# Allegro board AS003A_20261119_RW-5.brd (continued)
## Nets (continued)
DGND: BD1.1 BD2.1 BD3.1 BD4.1 BD5.1 BD6.1 BD7.1 BD8.1 BD9.1 BD10.1 BD11.1 BD12.1 C1.2 C2.2 C3.2 C4.2 C5.2 C6.2 C7.2 C8.2 C9.2 C10.2 C11.2 C12.2 C13.2 C14.2 C15.2 C16.2 C17.2 C18.2 C19.2 C20.2 C21.2 C22.2 C23.2 C24.2 C25.2 C26.2 C27.2 C28.2 C29.2 C30.2 C31.2 C32.2 C33.2 C34.2 C35.2 C36.2 C37.2 C38.2 C39.2 C40.2 C41.2 C42.2 C43.2 C44.2 C45.2 C46.2 C47.2 C48.2 C49.2 C50.2 C51.2 C52.2 C53.2 C54.2 C55.2 C56.2 C57.2 C58.2 C59.2 C60.2 C61.2 C62.2 C63.2 C64.2 C65.2 C66.2 C67.2 C68.2 C69.2 C70.2 C71.2 C72.2 C73.2 C74.2 C75.2 C76.2 C77.2 C78.2 C79.2 C80.2 C81.2 C82.2 C83.2 C84.2 C85.2 C86.2 C87.2 C88.2 C89.2 C90.2 C91.2 C92.2 C93.2 C94.2 C95.2 C96.2 C97.2 C98.2 C99.2 C100.2 C101.2 C102.2 C103.2 C104.2 C105.2 C106.2 C107.2 C108.2 C109.2 C110.2 C111.2 C112.2 C113.2 C114.2 C115.2 C116.2 C117.2 C118.2 C119.2 C120.2 C121.2 C122.2 C123.2 C124.2 C125.2 C126.2 C127.2 C128.2 C129.2 C130.2 C131.2 C132.2 C133.2 C134.2 C135.2 C136.2 C137.2 C138.2 C139.2 C140.2 C141.2 C142.2 C143.2 C144.2 C145.2 C146.2 C147.2 C148.2 C149.2 C150.2 C151.2 C152.2 C153.2 C154.2 C155.2 C156.2 C157.2 C158.2 C159.2 C160.2 C161.2 C162.2 C163.2 C164.2 C165.2 C166.2 C167.2 C168.2 C169.2 C170.2 C171.2 C172.2 C173.2 C174.2 C175.2 C176.2 C177.2 C178.2 C179.2 C180.2 C181.2 C182.2 C183.2 C184.2 C185.2 C186.2 C187.2 C188.2 C189.2 C190.2 C191.2 C192.2 C193.2 C194.2 C195.2 C196.2 C197.2 C198.2 C199.2 C200.2 C201.2 C202.2 C203.2 C204.2 C205.2 C206.2 C207.2 C208.2 C209.2 C210.2 C211.2 C212.2 C213.2 C214.2 C215.2 C216.2 C217.2 C218.2 C219.2 C220.2 C221.2 C222.2 C223.2 C224.2 C225.2 C226.2 C227.2 C228.2 C229.2 C230.2 C249.2 C250.2 C251.2 C285.2 C286.2 C287.2 C288.2 C289.2 C290.2 C291.2 C292.2 C293.2 C294.2 C295.2 C296.2 C297.2 C298.2 C299.2 C300.2 C332.2 C333.2 C334.2 C335.2 C336.2 C337.2 C338.2 C339.2 C340.2 C341.2 C342.2 C343.2 C344.2 C345.2 C346.2 C347.2 C348.2 C349.2 C350.2 C351.2 C352.2 C353.2 C354.2 C355.2 C356.2 C357.2 C358.2 C359.2 C360.2 C361.2 C362.2 C363.2 C364.2 C365.2 C366.2 C367.2 C368.2 C369.2 C370.2 C371.2 C372.2 C373.2 C374.2 C375.2 C376.2 C377.2 C378.2 C379.2 C380.2 C381.2 C382.2 C383.2 C384.2 C385.2 C386.2 C387.2 C388.2 C389.2 C390.2 C391.2 C392.2 C393.2 C394.2 C395.2 C396.2 C397.2 C398.2 C399.2 C400.2 C401.2 C402.2 C403.2 C404.2 C405.2 C406.2 C407.2 C408.2 C409.2 C410.2 C411.2 C412.2 C413.2 C414.2 C415.2 C416.2 C417.2 C418.2 C419.2 C420.2 C421.2 C422.2 C423.2 C424.2 C425.2 C426.2 C427.2 C428.2 C429.2 C430.2 C431.2 C432.2 C433.2 C434.2 C435.2 C436.2 C437.2 C438.2 C439.2 C440.2 C441.2 C442.2 C443.2 C444.2 C445.2 C446.2 C447.2 C448.2 C449.2 C450.2 C451.2 C452.2 C453.2 C454.2 C455.2 C456.2 C457.2 C458.2 C459.2 C460.2 C461.2 C462.2 C463.2 C464.2 C465.2 C466.2 C467.2 C468.2 C469.2 CSDPS225.B2 CSDPS225.B4 CSDPS225.B6 CSDPS225.B8 CSDPS225.B10 CSDPS225.B12 CSDPS225.B14 CSDPS225.B16 CSDPS225.C1 CSDPS225.C3 CSDPS225.C5 CSDPS225.C7 CSDPS225.C9 CSDPS225.C11 CSDPS225.C13 CSDPS225.C15 CSDPS226.B2 CSDPS226.B4 CSDPS226.B6 CSDPS226.B8 CSDPS226.B10 CSDPS226.B12 CSDPS226.B14 CSDPS226.B16 CSDPS226.C1 CSDPS226.C3 CSDPS226.C5 CSDPS226.C7 CSDPS226.C9 CSDPS226.C11 CSDPS226.C13 CSDPS226.C15 CSDPS229.B2 CSDPS229.B4 CSDPS229.B6 CSDPS229.B8 CSDPS229.B10 CSDPS229.B12 CSDPS229.B14 CSDPS229.B16 CSDPS229.C1 CSDPS229.C3 CSDPS229.C5 CSDPS229.C7 CSDPS229.C9 CSDPS229.C11 CSDPS229.C13 CSDPS229.C15 CSDPS425.B2 CSDPS425.B4 CSDPS425.B6 CSDPS425.B8 CSDPS425.B10 CSDPS425.B12 CSDPS425.B14 CSDPS425.B16 CSDPS425.C1 CSDPS425.C3 CSDPS425.C5 CSDPS425.C7 CSDPS425.C9 CSDPS425.C11 CSDPS425.C13 CSDPS425.C15 CSDPS426.B2 CSDPS426.B4 CSDPS426.B6 CSDPS426.B8 CSDPS426.B10 CSDPS426.B12 CSDPS426.B14 CSDPS426.B16 CSDPS426.C1 CSDPS426.C3 CSDPS426.C5 CSDPS426.C7 CSDPS426.C9 CSDPS426.C11 CSDPS426.C13 CSDPS426.C15 CSDPS429.B2 CSDPS429.B4 CSDPS429.B6 CSDPS429.B8 CSDPS429.B10 CSDPS429.B12 CSDPS429.B14 CSDPS429.B16 CSDPS429.C1 CSDPS429.C3 CSDPS429.C5 CSDPS429.C7 CSDPS429.C9 CSDPS429.C11 CSDPS429.C13 CSDPS429.C15 D101.A1 D101.A2 D101.A3 D101.A4 D101.A5 D101.A6 D101.A7 D101.A8 D101.A9 D101.A10 D101.A11 D101.A12 D101.A13 D101.A14 D101.A15 D101.A16 D101.B1 D101.B2 D101.B3 D101.B4 D101.B5 D101.B6 D101.B7 D101.B8 D101.B9 D101.B10 D101.B11 D101.B12 D101.B13 D101.B14 D101.B15 D101.B16 D102.A1 D102.A2 D102.A3 D102.A4 D102.A5 D102.A6 D102.A7 D102.A8 D102.A9 D102.A10 D102.A11 D102.A12 D102.A13 D102.A14 D102.A15 D102.A16 D102.B1 D102.B2 D102.B3 D102.B4 D102.B5 D102.B6 D102.B7 D102.B8 D102.B9 D102.B10 D102.B11 D102.B12 D102.B13 D102.B14 D102.B15 D102.B16 D103.A1 D103.A2 D103.A3 D103.A4 D103.A5 D103.A6 D103.A7 D103.A8 D103.A9 D103.A10 D103.A11 D103.A12 D103.A13 D103.A14 D103.A15 D103.A16 D103.B1 D103.B2 D103.B3 D103.B4 D103.B5 D103.B6 D103.B7 D103.B8 D103.B9 D103.B10 D103.B11 D103.B12 D103.B13 D103.B14 D103.B15 D103.B16 D104.A1 D104.A2 D104.A3 D104.A4 D104.A5 D104.A6 D104.A7 D104.A8 D104.A9 D104.A10 D104.A11 D104.A12 D104.A13 D104.A14 D104.A15 D104.A16 D104.B1 D104.B2 D104.B3 D104.B4 D104.B5 D104.B6 D104.B7 D104.B8 D104.B9 D104.B10 D104.B11 D104.B12 D104.B13 D104.B14 D104.B15 D104.B16 D105.A1 D105.A2 D105.A3 D105.A4 D105.A5 D105.A6 D105.A7 D105.A8 D105.A9 D105.A10 D105.A11 D105.A12 D105.A13 D105.A14 D105.A15 D105.A16 D105.B1 D105.B2 D105.B3 D105.B4 D105.B5 D105.B6 D105.B7 D105.B8 D105.B9 D105.B10 D105.B11 D105.B12 D105.B13 D105.B14 D105.B15 D105.B16 D106.A1 D106.A2 D106.A3 D106.A4 D106.A5 D106.A6 D106.A7 D106.A8 D106.A9 D106.A10 D106.A11 D106.A12 D106.A13 D106.A14 D106.A15 D106.A16 D106.B1 D106.B2 D106.B3 D106.B4 D106.B5 D106.B6 D106.B7 D106.B8 D106.B9 D106.B10 D106.B11 D106.B12 D106.B13 D106.B14 D106.B15 D106.B16 D107.A1 D107.A2 D107.A3 D107.A4 D107.A5 D107.A6 D107.A7 D107.A8 D107.A9 D107.A10 D107.A11 D107.A12 D107.A13 D107.A14 D107.A15 D107.A16 D107.B1 D107.B2 D107.B3 D107.B4 D107.B5 D107.B6 D107.B7 D107.B8 D107.B9 D107.B10 D107.B11 D107.B12 D107.B13 D107.B14 D107.B15 D107.B16 D108.A1 D108.A2 D108.A3 D108.A4 D108.A5 D108.A6 D108.A7 D108.A8 D108.A9 D108.A10 D108.A11 D108.A12 D108.A13 D108.A14 D108.A15 D108.A16 D108.B1 D108.B2 D108.B3 D108.B4 D108.B5 D108.B6 D108.B7 D108.B8 D108.B9 D108.B10 D108.B11 D108.B12 D108.B13 D108.B14 D108.B15 D108.B16 D109.A1 D109.A2 D109.A3 D109.A4 D109.A5 D109.A6 D109.A7 D109.A8 D109.A9 D109.A10 D109.A11 D109.A12 D109.A13 D109.A14 D109.A15 D109.A16 D109.B1 D109.B2 D109.B3 D109.B4 D109.B5 D109.B6 D109.B7 D109.B8 D109.B9 D109.B10 D109.B11 D109.B12 D109.B13 D109.B14 D109.B15 D109.B16 D110.A1 D110.A2 D110.A3 D110.A4 D110.A5 D110.A6 D110.A7 D110.A8 D110.A9 D110.A10 D110.A11 D110.A12 D110.A13 D110.A14 D110.A15 D110.A16 D110.B1 D110.B2 D110.B3 D110.B4 D110.B5 D110.B6 D110.B7 D110.B8 D110.B9 D110.B10 D110.B11 D110.B12 D110.B13 D110.B14 D110.B15 D110.B16 D111.A1 D111.A2 D111.A3 D111.A4 D111.A5 D111.A6 D111.A7 D111.A8 D111.A9 D111.A10 D111.A11 D111.A12 D111.A13 D111.A14 D111.A15 D111.A16 D111.B1 D111.B2 D111.B3 D111.B4 D111.B5 D111.B6 D111.B7 D111.B8 D111.B9 D111.B10 D111.B11 D111.B12 D111.B13 D111.B14 D111.B15 D111.B16 D112.A1 D112.A2 D112.A3 D112.A4 D112.A5 D112.A6 D112.A7 D112.A8 D112.A9 D112.A10 D112.A11 D112.A12 D112.A13 D112.A14 D112.A15 D112.A16 D112.B1 D112.B2 D112.B3 D112.B4 D112.B5 D112.B6 D112.B7 D112.B8 D112.B9 D112.B10 D112.B11 D112.B12 D112.B13 D112.B14 D112.B15 D112.B16 D113.A1 D113.A2 D113.A3 D113.A4 D113.A5 D113.A6 D113.A7 D113.A8 D113.A9 D113.A10 D113.A11 D113.A12 D113.A13 D113.A14 D113.A15 D113.A16 D113.B1 D113.B2 D113.B3 D113.B4 D113.B5 D113.B6 D113.B7 D113.B8 D113.B9 D113.B10 D113.B11 D113.B12 D113.B13 D113.B14 D113.B15 D113.B16 D114.A1 D114.A2 D114.A3 D114.A4 D114.A5 D114.A6 D114.A7 D114.A8 D114.A9 D114.A10 D114.A11 D114.A12 D114.A13 D114.A14 D114.A15 D114.A16 D114.B1 D114.B2 D114.B3 D114.B4 D114.B5 D114.B6 D114.B7 D114.B8 D114.B9 D114.B10 D114.B11 D114.B12 D114.B13 D114.B14 D114.B15 D114.B16 D115.A1 D115.A2 D115.A3 D115.A4 D115.A5 D115.A6 D115.A7 D115.A8 D115.A9 D115.A10 D115.A11 D115.A12 D115.A13 D115.A14 D115.A15 D115.A16 D115.B1 D115.B2 D115.B3 D115.B4 D115.B5 D115.B6 D115.B7 D115.B8 D115.B9 D115.B10 D115.B11 D115.B12 D115.B13 D115.B14 D115.B15 D115.B16 D116.A1 D116.A2 D116.A3 D116.A4 D116.A5 D116.A6 D116.A7 D116.A8 D116.A9 D116.A10 D116.A11 D116.A12 D116.A13 D116.A14 D116.A15 D116.A16 D116.B1 D116.B2 D116.B3 D116.B4 D116.B5 D116.B6 D116.B7 D116.B8 D116.B9 D116.B10 D116.B11 D116.B12 D116.B13 D116.B14 D116.B15 D116.B16 D117.A1 D117.A2 D117.A3 D117.A4 D117.A5 D117.A6 D117.A7 D117.A8 D117.A9 D117.A10 D117.A11 D117.A12 D117.A13 D117.A14 D117.A15 D117.A16 D117.B1 D117.B2 D117.B3 D117.B4 D117.B5 D117.B6 D117.B7 D117.B8 D117.B9 D117.B10 D117.B11 D117.B12 D117.B13 D117.B14 D117.B15 D117.B16 D118.A1 D118.A2 D118.A3 D118.A4 D118.A5 D118.A6 D118.A7 D118.A8 D118.A9 D118.A10 D118.A11 D118.A12 D118.A13 D118.A14 D118.A15 D118.A16 D118.B1 D118.B2 D118.B3 D118.B4 D118.B5 D118.B6 D118.B7 D118.B8 D118.B9 D118.B10 D118.B11 D118.B12 D118.B13 D118.B14 D118.B15 D118.B16 D119.A1 D119.A2 D119.A3 D119.A4 D119.A5 D119.A6 D119.A7 D119.A8 D119.A9 D119.A10 D119.A11 D119.A12 D119.A13 D119.A14 D119.A15 D119.A16 D119.B1 D119.B2 D119.B3 D119.B4 D119.B5 D119.B6 D119.B7 D119.B8 D119.B9 D119.B10 D119.B11 D119.B12 D119.B13 D119.B14 D119.B15 D119.B16 D120.A1 D120.A2 D120.A3 D120.A4 D120.A5 D120.A6 D120.A7 D120.A8 D120.A9 D120.A10 D120.A11 D120.A12 D120.A13 D120.A14 D120.A15 D120.A16 D120.B1 D120.B2 D120.B3 D120.B4 D120.B5 D120.B6 D120.B7 D120.B8 D120.B9 D120.B10 D120.B11 D120.B12 D120.B13 D120.B14 D120.B15 D120.B16 D121.A1 D121.A2 D121.A3 D121.A4 D121.A5 D121.A6 D121.A7 D121.A8 D121.A9 D121.A10 D121.A11 D121.A12 D121.A13 D121.A14 D121.A15 D121.A16 D121.B1 D121.B2 D121.B3 D121.B4 D121.B5 D121.B6 D121.B7 D121.B8 D121.B9 D121.B10 D121.B11 D121.B12 D121.B13 D121.B14 D121.B15 D121.B16 D122.A1 D122.A2 D122.A3 D122.A4 D122.A5 D122.A6 D122.A7 D122.A8 D122.A9 D122.A10 D122.A11 D122.A12 D122.A13 D122.A14 D122.A15 D122.A16 D122.B1 D122.B2 D122.B3 D122.B4 D122.B5 D122.B6 D122.B7 D122.B8 D122.B9 D122.B10 D122.B11 D122.B12 D122.B13 D122.B14 D122.B15 D122.B16 D123.A1 D123.A2 D123.A3 D123.A4 D123.A5 D123.A6 D123.A7 D123.A8 D123.A9 D123.A10 D123.A11 D123.A12 D123.A13 D123.A14 D123.A15 D123.A16 D123.B1 D123.B2 D123.B3 D123.B4 D123.B5 D123.B6 D123.B7 D123.B8 D123.B9 D123.B10 D123.B11 D123.B12 D123.B13 D123.B14 D123.B15 D123.B16 D124.A1 D124.A2 D124.A3 D124.A4 D124.A5 D124.A6 D124.A7 D124.A8 D124.A9 D124.A10 D124.A11 D124.A12 D124.A13 D124.A14 D124.A15 D124.A16 D124.B1 D124.B2 D124.B3 D124.B4 D124.B5 D124.B6 D124.B7 D124.B8 D124.B9 D124.B10 D124.B11 D124.B12 D124.B13 D124.B14 D124.B15 D124.B16 D125.A1 D125.A2 D125.A3 D125.A4 D125.A5 D125.A6 D125.A7 D125.A8 D125.A9 D125.A10 D125.A11 D125.A12 D125.A13 D125.A14 D125.A15 D125.A16 D125.B1 D125.B2 D125.B3 D125.B4 D125.B5 D125.B6 D125.B7 D125.B8 D125.B9 D125.B10 D125.B11 D125.B12 D125.B13 D125.B14 D125.B15 D125.B16 D126.A1 D126.A2 D126.A3 D126.A4 D126.A5 D126.A6 D126.A7 D126.A8 D126.A9 D126.A10 D126.A11 D126.A12 D126.A13 D126.A14 D126.A15 D126.A16 D126.B1 D126.B2 D126.B3 D126.B4 D126.B5 D126.B6 D126.B7 D126.B8 D126.B9 D126.B10 D126.B11 D126.B12 D126.B13 D126.B14 D126.B15 D126.B16 D127.A1 D127.A2 D127.A3 D127.A4 D127.A5 D127.A6 D127.A7 D127.A8 D127.A9 D127.A10 D127.A11 D127.A12 D127.A13 D127.A14 D127.A15 D127.A16 D127.B1 D127.B2 D127.B3 D127.B4 D127.B5 D127.B6 D127.B7 D127.B8 D127.B9 D127.B10 D127.B11 D127.B12 D127.B13 D127.B14 D127.B15 D127.B16 D128.A1 D128.A2 D128.A3 D128.A4 D128.A5 D128.A6 D128.A7 D128.A8 D128.A9 D128.A10 D128.A11 D128.A12 D128.A13 D128.A14 D128.A15 D128.A16 D128.B1 D128.B2 D128.B3 D128.B4 D128.B5 D128.B6 D128.B7 D128.B8 D128.B9 D128.B10 D128.B11 D128.B12 D128.B13 D128.B14 D128.B15 D128.B16 D129.A1 D129.A2 D129.A3 D129.A4 D129.A5 D129.A6 D129.A7 D129.A8 D129.A9 D129.A10 D129.A11 D129.A12 D129.A13 D129.A14 D129.A15 D129.A16 D129.B1 D129.B2 D129.B3 D129.B4 D129.B5 D129.B6 D129.B7 D129.B8 D129.B9 D129.B10 D129.B11 D129.B12 D129.B13 D129.B14 D129.B15 D129.B16 D130.A1 D130.A2 D130.A3 D130.A4 D130.A5 D130.A6 D130.A7 D130.A8 D130.A9 D130.A10 D130.A11 D130.A12 D130.A13 D130.A14 D130.A15 D130.A16 D130.B1 D130.B2 D130.B3 D130.B4 D130.B5 D130.B6 D130.B7 D130.B8 D130.B9 D130.B10 D130.B11 D130.B12 D130.B13 D130.B14 D130.B15 D130.B16 D131.A1 D131.A2 D131.A3 D131.A4 D131.A5 D131.A6 D131.A7 D131.A8 D131.A9 D131.A10 D131.A11 D131.A12 D131.A13 D131.A14 D131.A15 D131.A16 D131.B1 D131.B2 D131.B3 D131.B4 D131.B5 D131.B6 D131.B7 D131.B8 D131.B9 D131.B10 D131.B11 D131.B12 D131.B13 D131.B14 D131.B15 D131.B16 D132.A1 D132.A2 D132.A3 D132.A4 D132.A5 D132.A6 D132.A7 D132.A8 D132.A9 D132.A10 D132.A11 D132.A12 D132.A13 D132.A14 D132.A15 D132.A16 D132.B1 D132.B2 D132.B3 D132.B4 D132.B5 D132.B6 D132.B7 D132.B8 D132.B9 D132.B10 D132.B11 D132.B12 D132.B13 D132.B14 D132.B15 D132.B16 D217.A1 D217.A2 D217.A3 D217.A4 D217.A5 D217.A6 D217.A7 D217.A8 D217.A9 D217.A10 D217.A11 D217.A12 D217.A13 D217.A14 D217.A15 D217.A16 D217.B1 D217.B2 D217.B3 D217.B4 D217.B5 D217.B6 D217.B7 D217.B8 D217.B9 D217.B10 D217.B11 D217.B12 D217.B13 D217.B14 D217.B15 D217.B16 D218.A1 D218.A2 D218.A3 D218.A4 D218.A5 D218.A6 D218.A7 D218.A8 D218.A9 D218.A10 D218.A11 D218.A12 D218.A13 D218.A14 D218.A15 D218.A16 D218.B1 D218.B2 D218.B3 D218.B4 D218.B5 D218.B6 D218.B7 D218.B8 D218.B9 D218.B10 D218.B11 D218.B12 D218.B13 D218.B14 D218.B15 D218.B16 D219.A1 D219.A2 D219.A3 D219.A4 D219.A5 D219.A6 D219.A7 D219.A8 D219.A9 D219.A10 D219.A11 D219.A12 D219.A13 D219.A14 D219.A15 D219.A16 D219.B1 D219.B2 D219.B3 D219.B4 D219.B5 D219.B6 D219.B7 D219.B8 D219.B9 D219.B10 D219.B11 D219.B12 D219.B13 D219.B14 D219.B15 D219.B16 D220.A1 D220.A2 D220.A3 D220.A4 D220.A5 D220.A6 D220.A7 D220.A8 D220.A9 D220.A10 D220.A11 D220.A12 D220.A13 D220.A14 D220.A15 D220.A16 D220.B1 D220.B2 D220.B3 D220.B4 D220.B5 D220.B6 D220.B7 D220.B8 D220.B9 D220.B10 D220.B11 D220.B12 D220.B13 D220.B14 D220.B15 D220.B16 D221.A1 D221.A2 D221.A3 D221.A4 D221.A5 D221.A6 D221.A7 D221.A8 D221.A9 D221.A10 D221.A11 D221.A12 D221.A13 D221.A14 D221.A15 D221.A16 D221.B1 D221.B2 D221.B3 D221.B4 D221.B5 D221.B6 D221.B7 D221.B8 D221.B9 D221.B10 D221.B11 D221.B12 D221.B13 D221.B14 D221.B15 D221.B16 D222.A1 D222.A2 D222.A3 D222.A4 D222.A5 D222.A6 D222.A7 D222.A8 D222.A9 D222.A10 D222.A11 D222.A12 D222.A13 D222.A14 D222.A15 D222.A16 D222.B1 D222.B2 D222.B3 D222.B4 D222.B5 D222.B6 D222.B7 D222.B8 D222.B9 D222.B10 D222.B11 D222.B12 D222.B13 D222.B14 D222.B15 D222.B16 D223.A1 D223.A2 D223.A3 D223.A4 D223.A5 D223.A6 D223.A7 D223.A8 D223.A9 D223.A10 D223.A11 D223.A12 D223.A13 D223.A14 D223.A15 D223.A16 D223.B1 D223.B2 D223.B3 D223.B4 D223.B5 D223.B6 D223.B7 D223.B8 D223.B9 D223.B10 D223.B11 D223.B12 D223.B13 D223.B14 D223.B15 D223.B16 D224.A1 D224.A2 D224.A3 D224.A4 D224.A5 D224.A6 D224.A7 D224.A8 D224.A9 D224.A10 D224.A11 D224.A12 D224.A13 D224.A14 D224.A15 D224.A16 D224.B1 D224.B2 D224.B3 D224.B4 D224.B5 D224.B6 D224.B7 D224.B8 D224.B9 D224.B10 D224.B11 D224.B12 D224.B13 D224.B14 D224.B15 D224.B16 D227.A1 D227.A2 D227.A3 D227.A4 D227.A5 D227.A6 D227.A7 D227.A8 D227.A9 D227.A10 D227.A11 D227.A12 D227.A13 D227.A14 D227.A15 D227.A16 D227.A17 D227.B1 D227.B2 D227.B3 D227.B4 D227.B5 D227.B6 D227.B7 D227.B8 D227.B9 D227.B10 D227.B11 D227.B12 D227.B13 D227.B14 D227.B15 D227.B16 D227.B17 D228.A1 D228.A2 D228.A3 D228.A4 D228.A5 D228.A6 D228.A7 D228.A8 D228.A9 D228.A10 D228.A11 D228.A12 D228.A13 D228.A14 D228.A15 D228.A16 D228.A17 D228.B1 D228.B2 D228.B3 D228.B4 D228.B5 D228.B6 D228.B7 D228.B8 D228.B9 D228.B10 D228.B11 D228.B12 D228.B13 D228.B14 D228.B15 D228.B16 D228.B17 D231.A1 D231.A2 D231.A3 D231.A4 D231.A5 D231.A6 D231.A7 D231.A8 D231.A9 D231.A10 D231.A11 D231.A12 D231.A13 D231.A14 D231.A15 D231.A16 D231.A17 D231.B1 D231.B2 D231.B3 D231.B4 D231.B5 D231.B6 D231.B7 D231.B8 D231.B9 D231.B10 D231.B11 D231.B12 D231.B13 D231.B14 D231.B15 D231.B16 D231.B17 D232.A1 D232.A2 D232.A3 D232.A4 D232.A5 D232.A6 D232.A7 D232.A8 D232.A9 D232.A10 D232.A11 D232.A12 D232.A13 D232.A14 D232.A15 D232.A16 D232.A17 D232.B1 D232.B2 D232.B3 D232.B4 D232.B5 D232.B6 D232.B7 D232.B8 D232.B9 D232.B10 D232.B11 D232.B12 D232.B13 D232.B14 D232.B15 D232.B16 D232.B17 D301.A1 D301.A2 D301.A3 D301.A4 D301.A5 D301.A6 D301.A7 D301.A8 D301.A9 D301.A10 D301.A11 D301.A12 D301.A13 D301.A14 D301.A15 D301.A16 D301.B1 D301.B2 D301.B3 D301.B4 D301.B5 D301.B6 D301.B7 D301.B8 D301.B9 D301.B10 D301.B11 D301.B12 D301.B13 D301.B14 D301.B15 D301.B16 D302.A1 D302.A2 D302.A3 D302.A4 D302.A5 D302.A6 D302.A7 D302.A8 D302.A9 D302.A10 D302.A11 D302.A12 D302.A13 D302.A14 D302.A15 D302.A16 D302.B1 D302.B2 D302.B3 D302.B4 D302.B5 D302.B6 D302.B7 D302.B8 D302.B9 D302.B10 D302.B11 D302.B12 D302.B13 D302.B14 D302.B15 D302.B16 D303.A1 D303.A2 D303.A3 D303.A4 D303.A5 D303.A6 D303.A7 D303.A8 D303.A9 D303.A10 D303.A11 D303.A12 D303.A13 D303.A14 D303.A15 D303.A16 D303.B1 D303.B2 D303.B3 D303.B4 D303.B5 D303.B6 D303.B7 D303.B8 D303.B9 D303.B10 D303.B11 D303.B12 D303.B13 D303.B14 D303.B15 D303.B16 D304.A1 D304.A2 D304.A3 D304.A4 D304.A5 D304.A6 D304.A7 D304.A8 D304.A9 D304.A10 D304.A11 D304.A12 D304.A13 D304.A14 D304.A15 D304.A16 D304.B1 D304.B2 D304.B3 D304.B4 D304.B5 D304.B6 D304.B7 D304.B8 D304.B9 D304.B10 D304.B11 D304.B12 D304.B13 D304.B14 D304.B15 D304.B16 D305.A1 D305.A2 D305.A3 D305.A4 D305.A5 D305.A6 D305.A7 D305.A8 D305.A9 D305.A10 D305.A11 D305.A12 D305.A13 D305.A14 D305.A15 D305.A16 D305.B1 D305.B2 D305.B3 D305.B4 D305.B5 D305.B6 D305.B7 D305.B8 D305.B9 D305.B10 D305.B11 D305.B12 D305.B13 D305.B14 D305.B15 D305.B16 D306.A1 D306.A2 D306.A3 D306.A4 D306.A5 D306.A6 D306.A7 D306.A8 D306.A9 D306.A10 D306.A11 D306.A12 D306.A13 D306.A14 D306.A15 D306.A16 D306.B1 D306.B2 D306.B3 D306.B4 D306.B5 D306.B6 D306.B7 D306.B8 D306.B9 D306.B10 D306.B11 D306.B12 D306.B13 D306.B14 D306.B15 D306.B16 D307.A1 D307.A2 D307.A3 D307.A4 D307.A5 D307.A6 D307.A7 D307.A8 D307.A9 D307.A10 D307.A11 D307.A12 D307.A13 D307.A14 D307.A15 D307.A16 D307.B1 D307.B2 D307.B3 D307.B4 D307.B5 D307.B6 D307.B7 D307.B8 D307.B9 D307.B10 D307.B11 D307.B12 D307.B13 D307.B14 D307.B15 D307.B16 D308.A1 D308.A2 D308.A3 D308.A4 D308.A5 D308.A6 D308.A7 D308.A8 D308.A9 D308.A10 D308.A11 D308.A12 D308.A13 D308.A14 D308.A15 D308.A16 D308.B1 D308.B2 D308.B3 D308.B4 D308.B5 D308.B6 D308.B7 D308.B8 D308.B9 D308.B10 D308.B11 D308.B12 D308.B13 D308.B14 D308.B15 D308.B16 D309.A1 D309.A2 D309.A3 D309.A4 D309.A5 D309.A6 D309.A7 D309.A8 D309.A9 D309.A10 D309.A11 D309.A12 D309.A13 D309.A14 D309.A15 D309.A16 D309.B1 D309.B2 D309.B3 D309.B4 D309.B5 D309.B6 D309.B7 D309.B8 D309.B9 D309.B10 D309.B11 D309.B12 D309.B13 D309.B14 D309.B15 D309.B16 D310.A1 D310.A2 D310.A3 D310.A4 D310.A5 D310.A6 D310.A7 D310.A8 D310.A9 D310.A10 D310.A11 D310.A12 D310.A13 D310.A14 D310.A15 D310.A16 D310.B1 D310.B2 D310.B3 D310.B4 D310.B5 D310.B6 D310.B7 D310.B8 D310.B9 D310.B10 D310.B11 D310.B12 D310.B13 D310.B14 D310.B15 D310.B16 D311.A1 D311.A2 D311.A3 D311.A4 D311.A5 D311.A6 D311.A7 D311.A8 D311.A9 D311.A10 D311.A11 D311.A12 D311.A13 D311.A14 D311.A15 D311.A16 D311.B1 D311.B2 D311.B3 D311.B4 D311.B5 D311.B6 D311.B7 D311.B8 D311.B9 D311.B10 D311.B11 D311.B12 D311.B13 D311.B14 D311.B15 D311.B16 D312.A1 D312.A2 D312.A3 D312.A4 D312.A5 D312.A6 D312.A7 D312.A8 D312.A9 D312.A10 D312.A11 D312.A12 D312.A13 D312.A14 D312.A15 D312.A16 D312.B1 D312.B2 D312.B3 D312.B4 D312.B5 D312.B6 D312.B7 D312.B8 D312.B9 D312.B10 D312.B11 D312.B12 D312.B13 D312.B14 D312.B15 D312.B16 D313.A1 D313.A2 D313.A3 D313.A4 D313.A5 D313.A6 D313.A7 D313.A8 D313.A9 D313.A10 D313.A11 D313.A12 D313.A13 D313.A14 D313.A15 D313.A16 D313.B1 D313.B2 D313.B3 D313.B4 D313.B5 D313.B6 D313.B7 D313.B8 D313.B9 D313.B10 D313.B11 D313.B12 D313.B13 D313.B14 D313.B15 D313.B16 D314.A1 D314.A2 D314.A3 D314.A4 D314.A5 D314.A6 D314.A7 D314.A8 D314.A9 D314.A10 D314.A11 D314.A12 D314.A13 D314.A14 D314.A15 D314.A16 D314.B1 D314.B2 D314.B3 D314.B4 D314.B5 D314.B6 D314.B7 D314.B8 D314.B9 D314.B10 D314.B11 D314.B12 D314.B13 D314.B14 D314.B15 D314.B16 D315.A1 D315.A2 D315.A3 D315.A4 D315.A5 D315.A6 D315.A7 D315.A8 D315.A9 D315.A10 D315.A11 D315.A12 D315.A13 D315.A14 D315.A15 D315.A16 D315.B1 D315.B2 D315.B3 D315.B4 D315.B5 D315.B6 D315.B7 D315.B8 D315.B9 D315.B10 D315.B11 D315.B12 D315.B13 D315.B14 D315.B15 D315.B16 D316.A1 D316.A2 D316.A3 D316.A4 D316.A5 D316.A6 D316.A7 D316.A8 D316.A9 D316.A10 D316.A11 D316.A12 D316.A13 D316.A14 D316.A15 D316.A16 D316.B1 D316.B2 D316.B3 D316.B4 D316.B5 D316.B6 D316.B7 D316.B8 D316.B9 D316.B10 D316.B11 D316.B12 D316.B13 D316.B14 D316.B15 D316.B16 D317.A1 D317.A2 D317.A3 D317.A4 D317.A5 D317.A6 D317.A7 D317.A8 D317.A9 D317.A10 D317.A11 D317.A12 D317.A13 D317.A14 D317.A15 D317.A16 D317.B1 D317.B2 D317.B3 D317.B4 D317.B5 D317.B6 D317.B7 D317.B8 D317.B9 D317.B10 D317.B11 D317.B12 D317.B13 D317.B14 D317.B15 D317.B16 D318.A1 D318.A2 D318.A3 D318.A4 D318.A5 D318.A6 D318.A7 D318.A8 D318.A9 D318.A10 D318.A11 D318.A12 D318.A13 D318.A14 D318.A15 D318.A16 D318.B1 D318.B2 D318.B3 D318.B4 D318.B5 D318.B6 D318.B7 D318.B8 D318.B9 D318.B10 D318.B11 D318.B12 D318.B13 D318.B14 D318.B15 D318.B16 D319.A1 D319.A2 D319.A3 D319.A4 D319.A5 D319.A6 D319.A7 D319.A8 D319.A9 D319.A10 D319.A11 D319.A12 D319.A13 D319.A14 D319.A15 D319.A16 D319.B1 D319.B2 D319.B3 D319.B4 D319.B5 D319.B6 D319.B7 D319.B8 D319.B9 D319.B10 D319.B11 D319.B12 D319.B13 D319.B14 D319.B15 D319.B16 D320.A1 D320.A2 D320.A3 D320.A4 D320.A5 D320.A6 D320.A7 D320.A8 D320.A9 D320.A10 D320.A11 D320.A12 D320.A13 D320.A14 D320.A15 D320.A16 D320.B1 D320.B2 D320.B3 D320.B4 D320.B5 D320.B6 D320.B7 D320.B8 D320.B9 D320.B10 D320.B11 D320.B12 D320.B13 D320.B14 D320.B15 D320.B16 D321.A1 D321.A2 D321.A3 D321.A4 D321.A5 D321.A6 D321.A7 D321.A8 D321.A9 D321.A10 D321.A11 D321.A12 D321.A13 D321.A14 D321.A15 D321.A16 D321.B1 D321.B2 D321.B3 D321.B4 D321.B5 D321.B6 D321.B7 D321.B8 D321.B9 D321.B10 D321.B11 D321.B12 D321.B13 D321.B14 D321.B15 D321.B16 D322.A1 D322.A2 D322.A3 D322.A4 D322.A5 D322.A6 D322.A7 D322.A8 D322.A9 D322.A10 D322.A11 D322.A12 D322.A13 D322.A14 D322.A15 D322.A16 D322.B1 D322.B2 D322.B3 D322.B4 D322.B5 D322.B6 D322.B7 D322.B8 D322.B9 D322.B10 D322.B11 D322.B12 D322.B13 D322.B14 D322.B15 D322.B16 D323.A1 D323.A2 D323.A3 D323.A4 D323.A5 D323.A6 D323.A7 D323.A8 D323.A9 D323.A10 D323.A11 D323.A12 D323.A13 D323.A14 D323.A15 D323.A16 D323.B1 D323.B2 D323.B3 D323.B4 D323.B5 D323.B6 D323.B7 D323.B8 D323.B9 D323.B10 D323.B11 D323.B12 D323.B13 D323.B14 D323.B15 D323.B16 D427.A1 D427.A2 D427.A3 D427.A4 D427.A5 D427.A6 D427.A7 D427.A8 D427.A9 D427.A10 D427.A11 D427.A12 D427.A13 D427.A14 D427.A15 D427.A16 D427.A17 D427.B1 D427.B2 D427.B3 D427.B4 D427.B5 D427.B6 D427.B7 D427.B8 D427.B9 D427.B10 D427.B11 D427.B12 D427.B13 D427.B14 D427.B15 D427.B16 D427.B17 D428.A1 D428.A2 D428.A3 D428.A4 D428.A5 D428.A6 D428.A7 D428.A8 D428.A9 D428.A10 D428.A11 D428.A12 D428.A13 D428.A14 D428.A15 D428.A16 D428.A17 D428.B1 D428.B2 D428.B3 D428.B4 D428.B5 D428.B6 D428.B7 D428.B8 D428.B9 D428.B10 D428.B11 D428.B12 D428.B13 D428.B14 D428.B15 D428.B16 D428.B17 D431.A1 D431.A2 D431.A3 D431.A4 D431.A5 D431.A6 D431.A7 D431.A8 D431.A9 D431.A10 D431.A11 D431.A12 D431.A13 D431.A14 D431.A15 D431.A16 D431.A17 D431.B1 D431.B2 D431.B3 D431.B4 D431.B5 D431.B6 D431.B7 D431.B8 D431.B9 D431.B10 D431.B11 D431.B12 D431.B13 D431.B14 D431.B15 D431.B16 D431.B17 D432.A1 D432.A2 D432.A3 D432.A4 D432.A5 D432.A6 D432.A7 D432.A8 D432.A9 D432.A10 D432.A11 D432.A12 D432.A13 D432.A14 D432.A15 D432.A16 D432.A17 D432.B1 D432.B2 D432.B3 D432.B4 D432.B5 D432.B6 D432.B7 D432.B8 D432.B9 D432.B10 D432.B11 D432.B12 D432.B13 D432.B14 D432.B15 D432.B16 D432.B17 DPS1.A01 DPS1.A05 DPS1.A11 DPS1.A15 DPS1.B01 DPS1.B05 DPS1.B11 DPS1.B15 DPS1.C01 DPS1.C05 DPS1.C11 DPS1.C15 DPS2.A01 DPS2.A05 DPS2.A11 DPS2.A15 DPS2.B01 DPS2.B05 DPS2.B11 DPS2.B15 DPS2.C01 DPS2.C05 DPS2.C11 DPS2.C15 DPS3.A01 DPS3.A05 DPS3.A11 DPS3.A15 DPS3.B01 DPS3.B05 DPS3.B11 DPS3.B15 DPS3.C01 DPS3.C05 DPS3.C11 DPS3.C15 DPS4.A01 DPS4.A05 DPS4.A11 DPS4.A15 DPS4.B01 DPS4.B05 DPS4.B11 DPS4.B15 DPS4.C01 DPS4.C05 DPS4.C11 DPS4.C15 DPS7.A01 DPS7.A05 DPS7.A11 DPS7.A15 DPS7.B01 DPS7.B05 DPS7.B11 DPS7.B15 DPS7.C01 DPS7.C05 DPS7.C11 DPS7.C15 DPS8.A01 DPS8.A05 DPS8.A11 DPS8.A15 DPS8.B01 DPS8.B05 DPS8.B11 DPS8.B15 DPS8.C01 DPS8.C05 DPS8.C11 DPS8.C15 DUT_GND.1(TP) DUT_GND1.1(TP) DUT_GND2.1(TP) DUT_GND3.1(TP) DUT_GND4.1(TP) DUT_GND5.1(TP) K1.G1 K1.G2 K1.G3 K2.G1 K2.G2 K2.G3 K8.2 K8.7 K9.2 KS3.6(GND2) KS3.7(GND1) KS4.6(GND2) KS4.7(GND1) OSC1.2(GND) R3.1 R4.1 R7.1 R8.1 R13.1 R14.1 R19.1 R20.1 R25.1 R26.1 R31.1 R37.1 R38.1 R43.1 R49.1 R55.1 R56.1 R61.1 R62.1 R67.1 R68.1 R73.1 R74.1 R81.1 R104.2 R106.2 R108.2 R110.2 R112.2 R114.2 R119.2 R120.2 R121.2 R122.2 R186.1 R188.1 R191.1 R193.1 R196.1 R197.1 R209.1 R216.1 R217.1 R229.1 R235.2 R246.2 R247.2 R250.2 R251.2 R252.2 S1_PCIE_TX_N[0].2 S1_PCIE_TX_N[0].3 S1_PCIE_TX_N[0].4 S1_PCIE_TX_N[0].5 S1_PCIE_TX_N[1].2 S1_PCIE_TX_N[1].3 S1_PCIE_TX_N[1].4 S1_PCIE_TX_N[1].5 S1_PCIE_TX_N[2].2 S1_PCIE_TX_N[2].3 S1_PCIE_TX_N[2].4 S1_PCIE_TX_N[2].5 S1_PCIE_TX_N[3].2 S1_PCIE_TX_N[3].3 S1_PCIE_TX_N[3].4 S1_PCIE_TX_N[3].5 S1_PCIE_TX_N[4].2 S1_PCIE_TX_N[4].3 S1_PCIE_TX_N[4].4 S1_PCIE_TX_N[4].5 S1_PCIE_TX_N[5].2 S1_PCIE_TX_N[5].3 S1_PCIE_TX_N[5].4 S1_PCIE_TX_N[5].5 S1_PCIE_TX_N[6].2 S1_PCIE_TX_N[6].3 S1_PCIE_TX_N[6].4 S1_PCIE_TX_N[6].5 S1_PCIE_TX_N[7].2 S1_PCIE_TX_N[7].3 S1_PCIE_TX_N[7].4 S1_PCIE_TX_N[7].5 S1_PCIE_TX_P[0].2 S1_PCIE_TX_P[0].3 S1_PCIE_TX_P[0].4 S1_PCIE_TX_P[0].5 S1_PCIE_TX_P[1].2 S1_PCIE_TX_P[1].3 S1_PCIE_TX_P[1].4 S1_PCIE_TX_P[1].5 S1_PCIE_TX_P[2].2 S1_PCIE_TX_P[2].3 S1_PCIE_TX_P[2].4 S1_PCIE_TX_P[2].5 S1_PCIE_TX_P[3].2 S1_PCIE_TX_P[3].3 S1_PCIE_TX_P[3].4 S1_PCIE_TX_P[3].5 S1_PCIE_TX_P[4].2 S1_PCIE_TX_P[4].3 S1_PCIE_TX_P[4].4 S1_PCIE_TX_P[4].5 S1_PCIE_TX_P[5].2 S1_PCIE_TX_P[5].3 S1_PCIE_TX_P[5].4 S1_PCIE_TX_P[5].5 S1_PCIE_TX_P[6].2 S1_PCIE_TX_P[6].3 S1_PCIE_TX_P[6].4 S1_PCIE_TX_P[6].5 S1_PCIE_TX_P[7].2 S1_PCIE_TX_P[7].3 S1_PCIE_TX_P[7].4 S1_PCIE_TX_P[7].5 SB1.1 SB13.1 SB14.1 SB15.1 SB16.1 SB19.1 SITE1.A9(VSS[9]) SITE1.A11(VSS[1]) SITE1.A13(VSS[2]) SITE1.A15(VSS[3]) SITE1.A17(VSS[4]) SITE1.A19(VSS[5]) SITE1.A21(VSS[6]) SITE1.A23(VSS[7]) SITE1.A25(VSS[8]) SITE1.AA1(VSS[10]) SITE1.AA8(VSS[21]) SITE1.AA10(VSS[11]) SITE1.AA12(VSS[12]) SITE1.AA14(VSS[13]) SITE1.AA16(VSS[14]) SITE1.AA18(VSS[15]) SITE1.AA20(VSS[16]) SITE1.AA22(VSS[17]) SITE1.AA24(VSS[18]) SITE1.AA26(VSS[19]) SITE1.AA32(VSS[20]) SITE1.AB5(VSS[31]) SITE1.AB7(VSS[32]) SITE1.AB9(VSS[33]) SITE1.AB11(VSS[22]) SITE1.AB13(VSS[23]) SITE1.AB15(VSS[24]) SITE1.AB17(VSS[25]) SITE1.AB19(VSS[26]) SITE1.AB21(VSS[27]) SITE1.AB23(VSS[28]) SITE1.AB25(VSS[29]) SITE1.AB28(VSS[30]) SITE1.AC3(VSS[43]) SITE1.AC8(VSS[45]) SITE1.AC10(VSS[34]) SITE1.AC12(VSS[35]) SITE1.AC14(VSS[36]) SITE1.AC16(VSS[37]) SITE1.AC18(VSS[38]) SITE1.AC20(VSS[39]) SITE1.AC22(VSS[40]) SITE1.AC24(VSS[41]) SITE1.AC26(VSS[42]) SITE1.AC30(VSS[44]) SITE1.AD6(VSS[55]) SITE1.AD7(VSS[56]) SITE1.AD9(VSS[57]) SITE1.AD11(VSS[46]) SITE1.AD13(VSS[47]) SITE1.AD15(VSS[48]) SITE1.AD17(VSS[49]) SITE1.AD19(VSS[50]) SITE1.AD21(VSS[51]) SITE1.AD23(VSS[52]) SITE1.AD25(VSS[53]) SITE1.AD27(VSS[54]) SITE1.AE1(VSS[58]) SITE1.AE8(VSS[71]) SITE1.AE10(VSS[59]) SITE1.AE11(VSS[60]) SITE1.AE12(VSS[61]) SITE1.AE14(VSS[62]) SITE1.AE16(VSS[63]) SITE1.AE18(VSS[64]) SITE1.AE20(VSS[65]) SITE1.AE22(VSS[66]) SITE1.AE23(VSS[67]) SITE1.AE24(VSS[68]) SITE1.AE26(VSS[69]) SITE1.AE32(VSS[70]) SITE1.AF4(VSS[87]) SITE1.AF7(VSS[88]) SITE1.AF8(VSS[89]) SITE1.AF9(VSS[90]) SITE1.AF11(VSS[72]) SITE1.AF12(VSS[73]) SITE1.AF13(VSS[74]) SITE1.AF14(VSS[75]) SITE1.AF15(VSS[76]) SITE1.AF16(VSS[77]) SITE1.AF17(VSS[78]) SITE1.AF18(VSS[79]) SITE1.AF19(VSS[80]) SITE1.AF20(VSS[81]) SITE1.AF21(VSS[82]) SITE1.AF22(VSS[83]) SITE1.AF23(VSS[84]) SITE1.AF25(VSS[85]) SITE1.AF29(VSS[86]) SITE1.AG2(VSS[91]) SITE1.AG7(VSS[94]) SITE1.AG26(VSS[92]) SITE1.AG31(VSS[93]) SITE1.AH5(VSS[98]) SITE1.AH10(VSS[95]) SITE1.AH23(VSS[96]) SITE1.AH28(VSS[97]) SITE1.AJ3(VSS[100]) SITE1.AJ8(VSS[102]) SITE1.AJ25(VSS[99]) SITE1.AJ30(VSS[101]) SITE1.AK2(VSS[105]) SITE1.AK7(VSS[109]) SITE1.AK12(VSS[103]) SITE1.AK16(VSS[104]) SITE1.AK21(VSS[106]) SITE1.AK26(VSS[107]) SITE1.AK31(VSS[108]) SITE1.AL5(VSS[115]) SITE1.AL10(VSS[110]) SITE1.AL15(VSS[111]) SITE1.AL18(VSS[112]) SITE1.AL23(VSS[113]) SITE1.AL28(VSS[114]) SITE1.AM3(VSS[119]) SITE1.AM8(VSS[121]) SITE1.AM13(VSS[116]) SITE1.AM20(VSS[117]) SITE1.AM25(VSS[118]) SITE1.AM30(VSS[120]) SITE1.B3(VSS[131]) SITE1.B6(VSS[133]) SITE1.B9(VSS[134]) SITE1.B11(VSS[122]) SITE1.B13(VSS[123]) SITE1.B15(VSS[124]) SITE1.B17(VSS[125]) SITE1.B19(VSS[126]) SITE1.B21(VSS[127]) SITE1.B23(VSS[128]) SITE1.B25(VSS[129]) SITE1.B27(VSS[130]) SITE1.B30(VSS[132]) SITE1.C1(VSS[135]) SITE1.C4(VSS[154]) SITE1.C9(VSS[155]) SITE1.C10(VSS[136]) SITE1.C11(VSS[137]) SITE1.C12(VSS[138]) SITE1.C13(VSS[139]) SITE1.C14(VSS[140]) SITE1.C15(VSS[141]) SITE1.C16(VSS[142]) SITE1.C17(VSS[143]) SITE1.C18(VSS[144]) SITE1.C19(VSS[145]) SITE1.C20(VSS[146]) SITE1.C21(VSS[147]) SITE1.C22(VSS[148]) SITE1.C23(VSS[149]) SITE1.C24(VSS[150]) SITE1.C25(VSS[151]) SITE1.C29(VSS[152]) SITE1.C32(VSS[153]) SITE1.D8(VSS[164]) SITE1.D10(VSS[156]) SITE1.D12(VSS[157]) SITE1.D14(VSS[158]) SITE1.D16(VSS[159]) SITE1.D18(VSS[160]) SITE1.D20(VSS[161]) SITE1.D22(VSS[162]) SITE1.D24(VSS[163]) SITE1.E2(VSS[170]) SITE1.E5(VSS[176]) SITE1.E8(VSS[177]) SITE1.E10(VSS[165]) SITE1.E12(VSS[166]) SITE1.E14(VSS[167]) SITE1.E16(VSS[168]) SITE1.E18(VSS[169]) SITE1.E20(VSS[171]) SITE1.E22(VSS[172]) SITE1.E24(VSS[173]) SITE1.E28(VSS[174]) SITE1.E31(VSS[175]) SITE1.F7(VSS[193]) SITE1.F8(VSS[194]) SITE1.F9(VSS[195]) SITE1.F10(VSS[178]) SITE1.F11(VSS[179]) SITE1.F12(VSS[180]) SITE1.F13(VSS[181]) SITE1.F14(VSS[182]) SITE1.F15(VSS[183]) SITE1.F16(VSS[184]) SITE1.F17(VSS[185]) SITE1.F18(VSS[186]) SITE1.F19(VSS[187]) SITE1.F20(VSS[188]) SITE1.F21(VSS[189]) SITE1.F22(VSS[190]) SITE1.F23(VSS[191]) SITE1.F24(VSS[192]) SITE1.G3(VSS[211]) SITE1.G6(VSS[213]) SITE1.G8(VSS[214]) SITE1.G10(VSS[196]) SITE1.G11(VSS[197]) SITE1.G12(VSS[198]) SITE1.G13(VSS[199]) SITE1.G14(VSS[200]) SITE1.G16(VSS[201]) SITE1.G17(VSS[202]) SITE1.G18(VSS[203]) SITE1.G20(VSS[204]) SITE1.G21(VSS[205]) SITE1.G22(VSS[206]) SITE1.G23(VSS[207]) SITE1.G24(VSS[208]) SITE1.G26(VSS[209]) SITE1.G27(VSS[210]) SITE1.G30(VSS[212]) SITE1.H1(VSS[215]) SITE1.H4(VSS[229]) SITE1.H7(VSS[230]) SITE1.H9(VSS[231]) SITE1.H10(VSS[216]) SITE1.H11(VSS[217]) SITE1.H12(VSS[218]) SITE1.H14(VSS[219]) SITE1.H16(VSS[220]) SITE1.H18(VSS[221]) SITE1.H20(VSS[222]) SITE1.H21(VSS[223]) SITE1.H22(VSS[224]) SITE1.H23(VSS[225]) SITE1.H25(VSS[226]) SITE1.H29(VSS[227]) SITE1.H32(VSS[228]) SITE1.J8(VSS[246]) SITE1.J10(VSS[232]) SITE1.J12(VSS[233]) SITE1.J13(VSS[234]) SITE1.J14(VSS[235]) SITE1.J15(VSS[236]) SITE1.J16(VSS[237]) SITE1.J17(VSS[238]) SITE1.J18(VSS[239]) SITE1.J19(VSS[240]) SITE1.J20(VSS[241]) SITE1.J22(VSS[242]) SITE1.J23(VSS[243]) SITE1.J24(VSS[244]) SITE1.J26(VSS[245]) SITE1.K2(VSS[253]) SITE1.K5(VSS[259]) SITE1.K7(VSS[260]) SITE1.K9(VSS[261]) SITE1.K10(VSS[247]) SITE1.K11(VSS[248]) SITE1.K13(VSS[249]) SITE1.K15(VSS[250]) SITE1.K17(VSS[251]) SITE1.K19(VSS[252]) SITE1.K21(VSS[254]) SITE1.K23(VSS[255]) SITE1.K25(VSS[256]) SITE1.K28(VSS[257]) SITE1.K31(VSS[258]) SITE1.L4(VSS[273]) SITE1.L8(VSS[274]) SITE1.L10(VSS[262]) SITE1.L12(VSS[263]) SITE1.L14(VSS[264]) SITE1.L16(VSS[265]) SITE1.L18(VSS[266]) SITE1.L20(VSS[267]) SITE1.L22(VSS[268]) SITE1.L23(VSS[269]) SITE1.L24(VSS[270]) SITE1.L26(VSS[271]) SITE1.L29(VSS[272]) SITE1.M3(VSS[284]) SITE1.M7(VSS[286]) SITE1.M9(VSS[287]) SITE1.M10(VSS[275]) SITE1.M11(VSS[276]) SITE1.M13(VSS[277]) SITE1.M15(VSS[278]) SITE1.M17(VSS[279]) SITE1.M19(VSS[280]) SITE1.M21(VSS[281]) SITE1.M23(VSS[282]) SITE1.M25(VSS[283]) SITE1.M30(VSS[285]) SITE1.N1(VSS[288]) SITE1.N5(VSS[300]) SITE1.N8(VSS[301]) SITE1.N10(VSS[289]) SITE1.N12(VSS[290]) SITE1.N14(VSS[291]) SITE1.N16(VSS[292]) SITE1.N18(VSS[293]) SITE1.N20(VSS[294]) SITE1.N22(VSS[295]) SITE1.N24(VSS[296]) SITE1.N26(VSS[297]) SITE1.N28(VSS[298]) SITE1.N32(VSS[299]) SITE1.P7(VSS[310]) SITE1.P9(VSS[311]) SITE1.P11(VSS[302]) SITE1.P13(VSS[303]) SITE1.P15(VSS[304]) SITE1.P17(VSS[305]) SITE1.P19(VSS[306]) SITE1.P21(VSS[307]) SITE1.P23(VSS[308]) SITE1.P25(VSS[309]) SITE1.R2(VSS[317]) SITE1.R4(VSS[324]) SITE1.R8(VSS[325]) SITE1.R10(VSS[312]) SITE1.R12(VSS[313]) SITE1.R14(VSS[314]) SITE1.R16(VSS[315]) SITE1.R18(VSS[316]) SITE1.R20(VSS[318]) SITE1.R22(VSS[319]) SITE1.R24(VSS[320]) SITE1.R26(VSS[321]) SITE1.R29(VSS[322]) SITE1.R31(VSS[323]) SITE1.T1(VSS[326]) SITE1.T7(VSS[336]) SITE1.T9(VSS[337]) SITE1.T11(VSS[327]) SITE1.T13(VSS[328]) SITE1.T15(VSS[329]) SITE1.T17(VSS[330]) SITE1.T19(VSS[331]) SITE1.T21(VSS[332]) SITE1.T23(VSS[333]) SITE1.T25(VSS[334]) SITE1.T32(VSS[335]) SITE1.U5(VSS[348]) SITE1.U8(VSS[349]) SITE1.U10(VSS[338]) SITE1.U12(VSS[339]) SITE1.U14(VSS[340]) SITE1.U16(VSS[341]) SITE1.U18(VSS[342]) SITE1.U20(VSS[343]) SITE1.U22(VSS[344]) SITE1.U24(VSS[345]) SITE1.U26(VSS[346]) SITE1.U28(VSS[347]) SITE1.V2(VSS[355]) SITE1.V7(VSS[360]) SITE1.V9(VSS[361]) SITE1.V11(VSS[350]) SITE1.V13(VSS[351]) SITE1.V15(VSS[352]) SITE1.V17(VSS[353]) SITE1.V19(VSS[354]) SITE1.V21(VSS[356]) SITE1.V23(VSS[357]) SITE1.V25(VSS[358]) SITE1.V31(VSS[359]) SITE1.W4(VSS[372]) SITE1.W8(VSS[373]) SITE1.W10(VSS[362]) SITE1.W12(VSS[363]) SITE1.W14(VSS[364]) SITE1.W16(VSS[365]) SITE1.W18(VSS[366]) SITE1.W20(VSS[367]) SITE1.W22(VSS[368]) SITE1.W24(VSS[369]) SITE1.W26(VSS[370]) SITE1.W29(VSS[371]) SITE1.Y6(VSS[383]) SITE1.Y7(VSS[384]) SITE1.Y9(VSS[385]) SITE1.Y11(VSS[374]) SITE1.Y13(VSS[375]) SITE1.Y15(VSS[376]) SITE1.Y17(VSS[377]) SITE1.Y19(VSS[378]) SITE1.Y21(VSS[379]) SITE1.Y23(VSS[380]) SITE1.Y25(VSS[381]) SITE1.Y27(VSS[382]) U1.3(GND) U2.3(GND) U3.7(GND[2]) U3.20(GND[1]) U3.EPAD(THERMAL PAD) U4.3(GND) UHC230.G3 UHC230.G3_1 UHC230.G3_2 UHC230.G3_3 UHC230.G3_4 UHC230.G3_5 UHC230.G3_6 UHC230.G3_7 UHC230.G3_8 UHC230.G3_9 UHC230.G3_10 UHC230.G3_11 UHC230.G3_12 UHC230.G3_13 UHC230.G4 UHC230.G4_1 UHC230.G4_2 UHC230.G4_3 UHC230.G4_4 UHC230.G4_5 UHC230.G4_6 UHC230.G4_7 UHC230.G4_8 UHC230.G4_9 UHC230.G4_10 UHC230.G4_11 UHC230.G4_12 UHC230.G4_13 UHC430.G1 UHC430.G1_1 UHC430.G1_2 UHC430.G1_3 UHC430.G1_4 UHC430.G1_5 UHC430.G1_6 UHC430.G1_7 UHC430.G1_8 UHC430.G1_9 UHC430.G1_10 UHC430.G1_11 UHC430.G1_12 UHC430.G1_13 UHC430.G2 UHC430.G2_1 UHC430.G2_2 UHC430.G2_3 UHC430.G2_4 UHC430.G2_5 UHC430.G2_6 UHC430.G2_7 UHC430.G2_8 UHC430.G2_9 UHC430.G2_10 UHC430.G2_11 UHC430.G2_12 UHC430.G2_13
CSDPS225GS1: CSDPS225.D2
CSDPS225GS2: CSDPS225.A1
CSDPS225GS3: CSDPS225.D4
CSDPS225GS4: CSDPS225.A3
CSDPS225GS5: CSDPS225.D6
CSDPS225GS6: CSDPS225.A5
CSDPS225GS7: CSDPS225.D8
CSDPS225GS8: CSDPS225.A7
CSDPS225GS9: CSDPS225.D10
CSDPS225GS10: CSDPS225.A9
CSDPS225GS11: CSDPS225.D12
CSDPS225GS12: CSDPS225.A11
CSDPS225GS13: CSDPS225.D14
CSDPS225GS14: CSDPS225.A13
CSDPS225GS15: CSDPS225.D16
CSDPS225GS16: CSDPS225.A15
CSDPS225P1: CSDPS225.B1
CSDPS225P2: CSDPS225.C2
CSDPS225P3: CSDPS225.B3
CSDPS225P4: CSDPS225.C4
CSDPS225P5: CSDPS225.B5
CSDPS225P6: CSDPS225.C6
CSDPS225P7: CSDPS225.B7
CSDPS225P8: CSDPS225.C8
CSDPS225P9: CSDPS225.B9
CSDPS225P10: CSDPS225.C10
CSDPS225P11: CSDPS225.B11
CSDPS225P12: CSDPS225.C12
CSDPS225P13: CSDPS225.B13
CSDPS225P14: CSDPS225.C14
CSDPS225P15: CSDPS225.B15
CSDPS225P16: CSDPS225.C16
CSDPS225PS1: CSDPS225.D1
CSDPS225PS2: CSDPS225.A2
CSDPS225PS3: CSDPS225.D3
CSDPS225PS4: CSDPS225.A4
CSDPS225PS5: CSDPS225.D5
CSDPS225PS6: CSDPS225.A6
CSDPS225PS7: CSDPS225.D7
CSDPS225PS8: CSDPS225.A8
CSDPS225PS9: CSDPS225.D9
CSDPS225PS10: CSDPS225.A10
CSDPS225PS11: CSDPS225.D11
CSDPS225PS12: CSDPS225.A12
CSDPS225PS13: CSDPS225.D13
CSDPS225PS14: CSDPS225.A14
CSDPS225PS15: CSDPS225.D15
CSDPS225PS16: CSDPS225.A16
CSDPS226GS1: CSDPS226.D2
CSDPS226GS2: CSDPS226.A1
CSDPS226GS3: CSDPS226.D4
CSDPS226GS4: CSDPS226.A3
CSDPS226GS5: CSDPS226.D6
CSDPS226GS6: CSDPS226.A5
CSDPS226GS7: CSDPS226.D8
CSDPS226GS8: CSDPS226.A7
CSDPS226GS9: CSDPS226.D10
CSDPS226GS10: CSDPS226.A9
CSDPS226GS11: CSDPS226.D12
CSDPS226GS12: CSDPS226.A11
CSDPS226GS13: CSDPS226.D14
CSDPS226GS14: CSDPS226.A13
CSDPS226GS15: CSDPS226.D16
CSDPS226GS16: CSDPS226.A15
CSDPS226P1: CSDPS226.B1
CSDPS226P2: CSDPS226.C2
CSDPS226P3: CSDPS226.B3
CSDPS226P4: CSDPS226.C4
CSDPS226P5: CSDPS226.B5
CSDPS226P6: CSDPS226.C6
CSDPS226P7: CSDPS226.B7
CSDPS226P8: CSDPS226.C8
CSDPS226P9: CSDPS226.B9
CSDPS226P10: CSDPS226.C10
CSDPS226P11: CSDPS226.B11
CSDPS226P12: CSDPS226.C12
CSDPS226P13: CSDPS226.B13
CSDPS226P14: CSDPS226.C14
CSDPS226P15: CSDPS226.B15
CSDPS226P16: CSDPS226.C16
CSDPS226PS1: CSDPS226.D1
CSDPS226PS2: CSDPS226.A2
CSDPS226PS3: CSDPS226.D3
CSDPS226PS4: CSDPS226.A4
CSDPS226PS5: CSDPS226.D5
CSDPS226PS6: CSDPS226.A6
CSDPS226PS7: CSDPS226.D7
CSDPS226PS8: CSDPS226.A8
CSDPS226PS9: CSDPS226.D9
CSDPS226PS10: CSDPS226.A10
CSDPS226PS11: CSDPS226.D11
CSDPS226PS12: CSDPS226.A12
CSDPS226PS13: CSDPS226.D13
CSDPS226PS14: CSDPS226.A14
CSDPS226PS15: CSDPS226.D15
CSDPS226PS16: CSDPS226.A16
CSDPS226WW: CSDPS226.B17
CSDPS226XX: CSDPS226.C17
CSDPS229GS1: CSDPS229.D2
CSDPS229GS2: CSDPS229.A1
CSDPS229GS3: CSDPS229.D4
CSDPS229GS4: CSDPS229.A3
CSDPS229GS5: CSDPS229.D6
CSDPS229GS6: CSDPS229.A5
CSDPS229GS7: CSDPS229.D8
CSDPS229GS8: CSDPS229.A7
CSDPS229GS9: CSDPS229.D10
CSDPS229GS10: CSDPS229.A9
CSDPS229GS11: CSDPS229.D12
CSDPS229GS12: CSDPS229.A11
CSDPS229GS13: CSDPS229.D14
CSDPS229GS14: CSDPS229.A13
CSDPS229GS15: CSDPS229.D16
CSDPS229GS16: CSDPS229.A15
CSDPS229P1: CSDPS229.B1
CSDPS229P2: CSDPS229.C2
CSDPS229P3: CSDPS229.B3
CSDPS229P4: CSDPS229.C4
CSDPS229P5: CSDPS229.B5
CSDPS229P6: CSDPS229.C6
CSDPS229P7: CSDPS229.B7
CSDPS229P8: CSDPS229.C8
CSDPS229P9: CSDPS229.B9
CSDPS229P10: CSDPS229.C10
CSDPS229P11: CSDPS229.B11
CSDPS229P12: CSDPS229.C12
CSDPS229P13: CSDPS229.B13
CSDPS229P14: CSDPS229.C14
CSDPS229P15: CSDPS229.B15
CSDPS229P16: CSDPS229.C16
CSDPS229PS1: CSDPS229.D1
CSDPS229PS2: CSDPS229.A2
CSDPS229PS3: CSDPS229.D3
CSDPS229PS4: CSDPS229.A4
CSDPS229PS5: CSDPS229.D5
CSDPS229PS6: CSDPS229.A6
CSDPS229PS7: CSDPS229.D7
CSDPS229PS8: CSDPS229.A8
CSDPS229PS9: CSDPS229.D9
CSDPS229PS10: CSDPS229.A10
CSDPS229PS11: CSDPS229.D11
CSDPS229PS12: CSDPS229.A12
CSDPS229PS13: CSDPS229.D13
CSDPS229PS14: CSDPS229.A14
CSDPS229PS15: CSDPS229.D15
CSDPS229PS16: CSDPS229.A16
CSDPS425GS1: CSDPS425.D2
CSDPS425GS2: CSDPS425.A1
CSDPS425GS3: CSDPS425.D4
CSDPS425GS4: CSDPS425.A3
CSDPS425GS5: CSDPS425.D6
CSDPS425GS6: CSDPS425.A5
CSDPS425GS7: CSDPS425.D8
CSDPS425GS8: CSDPS425.A7
CSDPS425GS9: CSDPS425.D10
CSDPS425GS10: CSDPS425.A9
CSDPS425GS11: CSDPS425.D12
CSDPS425GS12: CSDPS425.A11
CSDPS425GS13: CSDPS425.D14
CSDPS425GS14: CSDPS425.A13
CSDPS425GS15: CSDPS425.D16
CSDPS425GS16: CSDPS425.A15
CSDPS425P1: CSDPS425.B1
CSDPS425P2: CSDPS425.C2
CSDPS425P3: CSDPS425.B3
CSDPS425P4: CSDPS425.C4
CSDPS425P5: CSDPS425.B5
CSDPS425P6: CSDPS425.C6
CSDPS425P7: CSDPS425.B7
CSDPS425P8: CSDPS425.C8
CSDPS425P9: CSDPS425.B9
CSDPS425P10: CSDPS425.C10
CSDPS425P11: CSDPS425.B11
CSDPS425P12: CSDPS425.C12
CSDPS425P13: CSDPS425.B13
CSDPS425P14: CSDPS425.C14
CSDPS425P15: CSDPS425.B15
CSDPS425P16: CSDPS425.C16
CSDPS425PS1: CSDPS425.D1
CSDPS425PS2: CSDPS425.A2
CSDPS425PS3: CSDPS425.D3
CSDPS425PS4: CSDPS425.A4
CSDPS425PS5: CSDPS425.D5
CSDPS425PS6: CSDPS425.A6
CSDPS425PS7: CSDPS425.D7
CSDPS425PS8: CSDPS425.A8
CSDPS425PS9: CSDPS425.D9
CSDPS425PS10: CSDPS425.A10
CSDPS425PS11: CSDPS425.D11
CSDPS425PS12: CSDPS425.A12
CSDPS425PS13: CSDPS425.D13
CSDPS425PS14: CSDPS425.A14
CSDPS425PS15: CSDPS425.D15
CSDPS425PS16: CSDPS425.A16
CSDPS426GS1: CSDPS426.D2
CSDPS426GS2: CSDPS426.A1
CSDPS426GS3: CSDPS426.D4
CSDPS426GS4: CSDPS426.A3
CSDPS426GS5: CSDPS426.D6
CSDPS426GS6: CSDPS426.A5
CSDPS426GS7: CSDPS426.D8
CSDPS426GS8: CSDPS426.A7
CSDPS426GS9: CSDPS426.D10
CSDPS426GS10: CSDPS426.A9
CSDPS426GS11: CSDPS426.D12
CSDPS426GS12: CSDPS426.A11
CSDPS426GS13: CSDPS426.D14
CSDPS426GS14: CSDPS426.A13
CSDPS426GS15: CSDPS426.D16
CSDPS426GS16: CSDPS426.A15
CSDPS426P1: CSDPS426.B1
CSDPS426P2: CSDPS426.C2
CSDPS426P3: CSDPS426.B3
CSDPS426P4: CSDPS426.C4
CSDPS426P5: CSDPS426.B5
CSDPS426P6: CSDPS426.C6
CSDPS426P7: CSDPS426.B7
CSDPS426P8: CSDPS426.C8
CSDPS426P9: CSDPS426.B9
CSDPS426P10: CSDPS426.C10
CSDPS426P11: CSDPS426.B11
CSDPS426P12: CSDPS426.C12
CSDPS426P13: CSDPS426.B13
CSDPS426P14: CSDPS426.C14
CSDPS426P15: CSDPS426.B15
CSDPS426P16: CSDPS426.C16
CSDPS426PS1: CSDPS426.D1
CSDPS426PS2: CSDPS426.A2
CSDPS426PS3: CSDPS426.D3
CSDPS426PS4: CSDPS426.A4
CSDPS426PS5: CSDPS426.D5
CSDPS426PS6: CSDPS426.A6
CSDPS426PS7: CSDPS426.D7
CSDPS426PS8: CSDPS426.A8
CSDPS426PS9: CSDPS426.D9
CSDPS426PS10: CSDPS426.A10
CSDPS426PS11: CSDPS426.D11
CSDPS426PS12: CSDPS426.A12
CSDPS426PS13: CSDPS426.D13
CSDPS426PS14: CSDPS426.A14
CSDPS426PS15: CSDPS426.D15
CSDPS426PS16: CSDPS426.A16
CSDPS426WW: CSDPS426.B17
CSDPS426XX: CSDPS426.C17
CSDPS429GS1: CSDPS429.D2
CSDPS429GS2: CSDPS429.A1
CSDPS429GS3: CSDPS429.D4
CSDPS429GS4: CSDPS429.A3
CSDPS429GS5: CSDPS429.D6
CSDPS429GS6: CSDPS429.A5
CSDPS429GS7: CSDPS429.D8
CSDPS429GS8: CSDPS429.A7
CSDPS429GS9: CSDPS429.D10
CSDPS429GS10: CSDPS429.A9
CSDPS429GS11: CSDPS429.D12
CSDPS429GS12: CSDPS429.A11
CSDPS429GS13: CSDPS429.D14
CSDPS429GS14: CSDPS429.A13
CSDPS429GS15: CSDPS429.D16
CSDPS429GS16: CSDPS429.A15
CSDPS429P1: CSDPS429.B1
CSDPS429P2: CSDPS429.C2
CSDPS429P3: CSDPS429.B3
CSDPS429P4: CSDPS429.C4
CSDPS429P5: CSDPS429.B5
CSDPS429P6: CSDPS429.C6
CSDPS429P7: CSDPS429.B7
CSDPS429P8: CSDPS429.C8
CSDPS429P9: CSDPS429.B9
CSDPS429P10: CSDPS429.C10
CSDPS429P11: CSDPS429.B11
CSDPS429P12: CSDPS429.C12
CSDPS429P13: CSDPS429.B13
CSDPS429P14: CSDPS429.C14
CSDPS429P15: CSDPS429.B15
CSDPS429P16: CSDPS429.C16
CSDPS429PS1: CSDPS429.D1
CSDPS429PS2: CSDPS429.A2
CSDPS429PS3: CSDPS429.D3
CSDPS429PS4: CSDPS429.A4
CSDPS429PS5: CSDPS429.D5
CSDPS429PS6: CSDPS429.A6
CSDPS429PS7: CSDPS429.D7
CSDPS429PS8: CSDPS429.A8
CSDPS429PS9: CSDPS429.D9
CSDPS429PS10: CSDPS429.A10
CSDPS429PS11: CSDPS429.D11
CSDPS429PS12: CSDPS429.A12
CSDPS429PS13: CSDPS429.D13
CSDPS429PS14: CSDPS429.A14
CSDPS429PS15: CSDPS429.D15
CSDPS429PS16: CSDPS429.A16
D227_4_TRIG: D227.04
D228_4_TRIG: D228.04
D231_MCB1_CT2: D231.17 TR3.1
D231_MCB1_E+: D231.16
D231_MCB1_E-: D231.15
D231_MCB1_EE+: D231.08
D231_MCB1_EE-: D231.07
D231_MCB1_F+: D231.14
D231_MCB1_F-: D231.13
D231_MCB1_FF+: D231.06
D231_MCB1_FF-: D231.05
D231_MCB1_G+: D231.12
D231_MCB1_G-: D231.11
D231_MCB1_GG+: D231.04
D231_MCB1_GG-: D231.03
D231_MCB1_H+: D231.10
D231_MCB1_H-: D231.09
D231_MCB1_HH+: D231.02
D231_MCB1_HH-: D231.01
D232_4_TRIG: D232.04
D232_MCB1_CT2: D232.17
D232_MCB1_E+: D232.16
D232_MCB1_E-: D232.15
D232_MCB1_EE+: D232.08
D232_MCB1_EE-: D232.07
D232_MCB1_F+: D232.14
D232_MCB1_F-: D232.13
D232_MCB1_FF+: D232.06
D232_MCB1_FF-: D232.05
D232_MCB1_G+: D232.12
D232_MCB1_G-: D232.11
D232_MCB1_GG-: D232.03
D232_MCB1_H+: D232.10
D232_MCB1_H-: D232.09
D232_MCB1_HH+: D232.02
D232_MCB1_HH-: D232.01
D431_MCB1_A+: D431.16
D431_MCB1_A-: D431.15
D431_MCB1_AA+: D431.08
D431_MCB1_AA-: D431.07
D431_MCB1_B+: D431.14
D431_MCB1_B-: D431.13
D431_MCB1_BB+: D431.06
D431_MCB1_BB-: D431.05
D431_MCB1_C+: D431.12
D431_MCB1_C-: D431.11
D431_MCB1_CC+: D431.04
D431_MCB1_CC-: D431.03
D431_MCB1_CT1: D431.17 TR2.1
D431_MCB1_D+: D431.10
D431_MCB1_D-: D431.09
D431_MCB1_DD+: D431.02
D431_MCB1_DD-: D431.01
D432_MCB1_A+: D432.16
D432_MCB1_A-: D432.15
D432_MCB1_AA+: D432.08
D432_MCB1_AA-: D432.07
D432_MCB1_B+: D432.14
D432_MCB1_B-: D432.13
D432_MCB1_BB+: D432.06
D432_MCB1_BB-: D432.05
D432_MCB1_C+: D432.12
D432_MCB1_C-: D432.11
D432_MCB1_CC+: D432.04
D432_MCB1_CC-: D432.03
D432_MCB1_CT1: D432.17
D432_MCB1_D+: D432.10
D432_MCB1_D-: D432.09
D432_MCB1_DD+: D432.02
D432_MCB1_DD-: D432.01
D10101: D101.01 SITE1.AG12(GPIO[15])
D10102: D101.02 SITE1.AL26(D5C1_DQS1_B_T)
D10103: D101.03 SITE1.AG17(PIN_RESET_N)
D10104: D101.04 SITE1.AM26(D5C1_DQS1_B_C)
D10105: D101.05 SITE1.AG19(GPIO[9])
D10106: D101.06 SITE1.AM29(D5C1_DQS4_B_T)
D10107: D101.07 SITE1.AH25(D5C1_DQ20_B)
D10108: D101.08 SITE1.AL29(D5C1_DQS4_B_C)
D10109: D101.09 SITE1.AH27(D5C1_DQ18_B)
D10110: D101.10 SITE1.AL31(D5C1_DQS9_B_T)
D10111: D101.11 SITE1.AG28(D5C1_DQ5_B)
D10112: D101.12 SITE1.AM31(D5C1_DQS9_B_C)
D10113: D101.13 SITE1.AF28(D5C1_CID2_NC)
D10114: D101.14 SITE1.AH31(D5C1_DQS0_B_T)
D10115: D101.15 SITE1.AE28(D5C1_CID0_NC)
D10116: D101.16 SITE1.AJ31(D5C1_DQS0_B_C)
D10201: D102.01 SITE1.AK13(D5C0_DQ4_A)
D10202: D102.02 SITE1.AH21(GPIO[4])
D10203: D102.03 SITE1.AH22(GPIO[1])
D10204: D102.04 K7.2
D10205: D102.05 SITE1.AC29(D5C1_ODT0_NC)
D10206: D102.06 SITE1.AJ24(D5C1_DQS7_B_T)
D10207: D102.07 SITE1.AB29(D5C1_CA10_A)
D10208: D102.08 SITE1.AH24(D5C1_DQS7_B_C)
D10209: D102.09 SITE1.AA29(D5C1_CA8_A)
D10210: D102.10 SITE1.AH26(D5C1_DQS2_B_T)
D10211: D102.11 SITE1.Y29(D5C1_CA6_A)
D10212: D102.12 SITE1.AJ26(D5C1_DQS2_B_C)
D10213: D102.13 SITE1.W27(D5C1_CA3_A)
D10214: D102.14 SITE1.AJ29(D5C1_DQS5_B_T)
D10215: D102.15 SITE1.U29(D5C1_CA1_A)
D10216: D102.16 SITE1.AH29(D5C1_DQS5_B_C)
D10301: D103.01 SITE1.AL27(D5C1_DQ9_B)
D10302: D103.02 SITE1.AK14(D5C0_DQ1_A)
D10303: D103.03 SITE1.AL30(D5C1_CB0_B)
D10304: D103.04 SITE1.AK15(D5C0_DQ2_A)
D10305: D103.05 SITE1.AG27(D5C1_DQ17_B)
D10306: D103.06 SITE1.AK17(SLV_SCL)
D10307: D103.07 SITE1.AE31(D5C1_CS1_B_N)
D10308: D103.08 SITE1.AK18(D5C1_DQ29_B)
D10309: D103.09 SITE1.AC31(D5C1_CA1_B)
D10310: D103.10 SITE1.AK19(D5C1_DQ30_B)
D10311: D103.11 SITE1.AA31(D5C1_CA3_B)
D10312: D103.12 SITE1.AK20(D5C1_DQ27_B)
D10313: D103.13 SITE1.W31(D5C1_CA7_B)
D10314: D103.14 SITE1.AK22(D5C1_DQ24_B)
D10315: D103.15 SITE1.U31(D5C1_CA10_B)
D10316: D103.16 SITE1.AK23(D5C1_DQ13_B)
D10401: D104.01 SITE1.AG14(GPIO[21])
D10402: D104.02 SITE1.AM15(D5C0_DQ0_A)
D10403: D104.03 SITE1.AM16(XOUT)
D10404: D104.04 SITE1.AM17(DDR_SDA)
D10405: D104.05 SITE1.AM18(D5C1_DQ31_B)
D10406: D104.06 SITE1.AG20(GPIO[6])
D10407: D104.07 SITE1.AG21(GPIO[3])
D10408: D104.08 SITE1.AM22(D5C1_DQ26_B)
D10409: D104.09 SITE1.AM23(D5C1_DQ15_B)
D10410: D104.10 SITE1.AG24(D5C1_DQ22_B)
D10411: D104.11 SITE1.AG25(D5C1_DQ19_B)
D10412: D104.12 SITE1.AM27(D5C1_DQ10_B)
D10413: D104.13 SITE1.AM28(D5C1_CB3_B)
D10414: D104.14 SITE1.AM32(D5C1_CB6_B)
D10415: D104.15 SITE1.AL32(D5C1_CB5_B)
D10416: D104.16 SITE1.AK32(D5C1_CB4_B)
D10501: D105.01 SITE1.AC27(D5C1_CA11_A)
D10502: D105.02 SITE1.AF32(D5C1_CK1_B_T)
D10503: D105.03 SITE1.AC28(D5C1_CA12_A)
D10504: D105.04 SITE1.AF31(D5C1_CK1_B_C)
D10505: D105.05 SITE1.AA28(D5C1_CA7_A)
D10506: D105.06 SITE1.AD31(D5C1_CK0_B_T)
D10507: D105.07 SITE1.Y28(D5C1_CA5_A)
D10508: D105.08 SITE1.AD32(D5C1_CK0_B_C)
D10509: D105.09 SITE1.W28(D5C1_CA4_A)
D10510: D105.10 SITE1.AB32(D5C1_CK2_B_T)
D10511: D105.11 SITE1.V27(D5C1_CA2_A)
D10512: D105.12 SITE1.AB31(D5C1_CK2_B_C)
D10513: D105.13 SITE1.U27(D5C1_CA0_A)
D10514: D105.14 SITE1.Y31(D5C1_CK3_B_T)
D10515: D105.15 SITE1.R28(D5C1_CS2_A_N)
D10516: D105.16 SITE1.Y32(D5C1_CK3_B_C)
D10601: D106.01 SITE1.AD28(D5C1_ODT2_NC)
D10602: D106.02 SITE1.T27(D5C1_CS3_A_N)
D10603: D106.03 SITE1.N29(D5C1_CS0_A_N)
D10604: D106.04 SITE1.L27(D5C1_PWR_GOOD)
D10605: D106.05 SITE1.K29(D5C1_DQ31_A)
D10606: D106.06 SITE1.V29(D5C1_CK2_A_T)
D10607: D106.07 SITE1.F29(D5C1_DQ24_A)
D10608: D106.08 SITE1.V28(D5C1_CK2_A_C)
D10609: D106.09 SITE1.E29(D5C1_DQ15_A)
D10610: D106.10 SITE1.T29(D5C1_CK1_A_T)
D10611: D106.11 SITE1.D27(D5C1_DQ14_A)
D10612: D106.12 SITE1.T28(D5C1_CK1_A_C)
D10613: D106.13 SITE1.D26(GPIO[28])
D10614: D106.14 SITE1.P29(D5C1_CK0_A_T)
D10615: D106.15 SITE1.D25(PCIE_CLKREQ_N)
D10616: D106.16 SITE1.P28(D5C1_CK0_A_C)
D10701: D107.01 SITE1.T31(D5C1_CA13_B)
D10702: D107.02 SITE1.AK24(D5C1_DQ14_B)
D10703: D107.03 SITE1.R27(D5C1_CS1_A_N)
D10704: D107.04 SITE1.AK25(D5C1_DQ11_B)
D10705: D107.05 SITE1.N31(D5C1_CB4_A)
D10706: D107.06 SITE1.AK27(D5C1_DQ8_B)
D10707: D107.07 SITE1.L31(D5C1_CB1_A)
D10708: D107.08 SITE1.AK28(D5C1_CB1_B)
D10709: D107.09 SITE1.K27(D5C1_DQ29_A)
D10710: D107.10 SITE1.AK29(D5C1_CB2_B)
D10711: D107.11 SITE1.H31(D5C1_DQ20_A)
D10712: D107.12 SITE1.AK30(D5C1_CB7_B)
D10713: D107.13 SITE1.F31(D5C1_DQ17_A)
D10714: D107.14 SITE1.AH30(D5C1_DQ4_B)
D10715: D107.15 SITE1.C31(D5C1_DQ4_A)
D10716: D107.16 SITE1.AG30(D5C1_DQ3_B)
D10801: D108.01 SITE1.AJ32(D5C1_DQ0_B)
D10802: D108.02 SITE1.AH32(D5C1_DQ2_B)
D10803: D108.03 SITE1.AG32(D5C1_DQ1_B)
D10804: D108.04 SITE1.AF27(D5C1_CID1_NC)
D10805: D108.05 SITE1.AE27(D5C1_ODT1_NC)
D10806: D108.06 SITE1.AC32(D5C1_PAR_B)
D10807: D108.07 SITE1.AB27(D5C1_CA9_A)
D10808: D108.08 SITE1.AA27(D5C1_PAR_A)
D10809: D108.09 SITE1.W32(D5C1_CA4_B)
D10810: D108.10 SITE1.V32(D5C1_CA8_B)
D10811: D108.11 SITE1.U32(D5C1_CA11_B)
D10812: D108.12 SITE1.R32(D5C1_CB7_A)
D10813: D108.13 SITE1.P27(D5C1_ALERT1_N)
D10814: D108.14 SITE1.N27(D5C1_MEMRESET_N)
D10815: D108.15 SITE1.L32(D5C1_CB2_A)
D10816: D108.16 SITE1.K32(D5C1_DQ23_A)
D10901: D109.01 R126.2
D10902: D109.02 R124.2
D10903: D109.03 R125.2
D10904: D109.04 R123.2
D10905: D109.05 R118.2
D10906: D109.06 R128.2
D10907: D109.07 R117.2
D10908: D109.08 R127.2
D10909: D109.09 R136.2
D10910: D109.10 R130.2
D10911: D109.11 R135.2
D10912: D109.12 R129.2
D10913: D109.13 R132.2
D10914: D109.14 R134.2
D10915: D109.15 R131.2
D10916: D109.16 R133.2
D11001: D110.01 SITE1.F28(D5C1_DQ26_A)
D11002: D110.02 SITE1.P31(D5C1_DQS9_A_T)
D11003: D110.03 SITE1.E27(D5C1_DQ13_A)
D11004: D110.04 SITE1.P32(D5C1_DQS9_A_C)
D11005: D110.05 SITE1.E26(GPIO[27])
D11006: D110.06 SITE1.M32(D5C1_DQS4_A_T)
D11007: D110.07 SITE1.E25(PCIE_WAKE_N)
D11008: D110.08 SITE1.M31(D5C1_DQS4_A_C)
D11009: D110.09 SITE1.U30(D5C1_CA12_B)
D11010: D110.10 SITE1.J32(D5C1_DQS7_A_T)
D11011: D110.11 SITE1.R30(D5C1_CB5_A)
D11012: D110.12 SITE1.J31(D5C1_DQS7_A_C)
D11013: D110.13 SITE1.N30(D5C1_CB3_A)
D11014: D110.14 SITE1.G31(D5C1_DQS2_A_T)
D11015: D110.15 SITE1.K30(D5C1_DQ21_A)
D11016: D110.16 SITE1.G32(D5C1_DQS2_A_C)
D11101: D111.01 K6.4
D11102: D111.02 SITE1.M29(D5C1_CK3_A_T)
D11103: D111.03 SITE1.L28(D5C1_ATBPAD)
D11104: D111.04 SITE1.M28(D5C1_CK3_A_C)
D11105: D111.05 SITE1.H28(D5C1_DQ28_A)
D11106: D111.06 SITE1.J29(D5C1_DQS8_A_T)
D11107: D111.07 SITE1.W30(D5C1_CA6_B)
D11108: D111.08 SITE1.J28(D5C1_DQS8_A_C)
D11109: D111.09 SITE1.J27(D5C1_DQ30_A)
D11110: D111.10 SITE1.G28(D5C1_DQS3_A_T)
D11111: D111.11 SITE1.H27(D5C1_DQ27_A)
D11112: D111.12 SITE1.G29(D5C1_DQS3_A_C)
D11113: D111.13 SITE1.F32(D5C1_DQ18_A)
D11114: D111.14 SITE1.D29(D5C1_DQS6_A_T)
D11115: D111.15 SITE1.E32(D5C1_DQ7_A)
D11116: D111.16 SITE1.D28(D5C1_DQS6_A_C)
D11201: D112.01 K2.6
D11202: D112.02 SITE1.AE30(D5C1_CS2_B_N)
D11203: D112.03 K2.4
D11204: D112.04 SITE1.AB30(D5C1_CA0_B)
D11205: D112.05 K1.6
D11206: D112.06 SITE1.Y30(D5C1_CA5_B)
D11207: D112.07 K1.4
D11208: D112.08 SITE1.V30(D5C1_CA9_B)
D11209: D112.09 SITE1.B26(GPIO[30])
